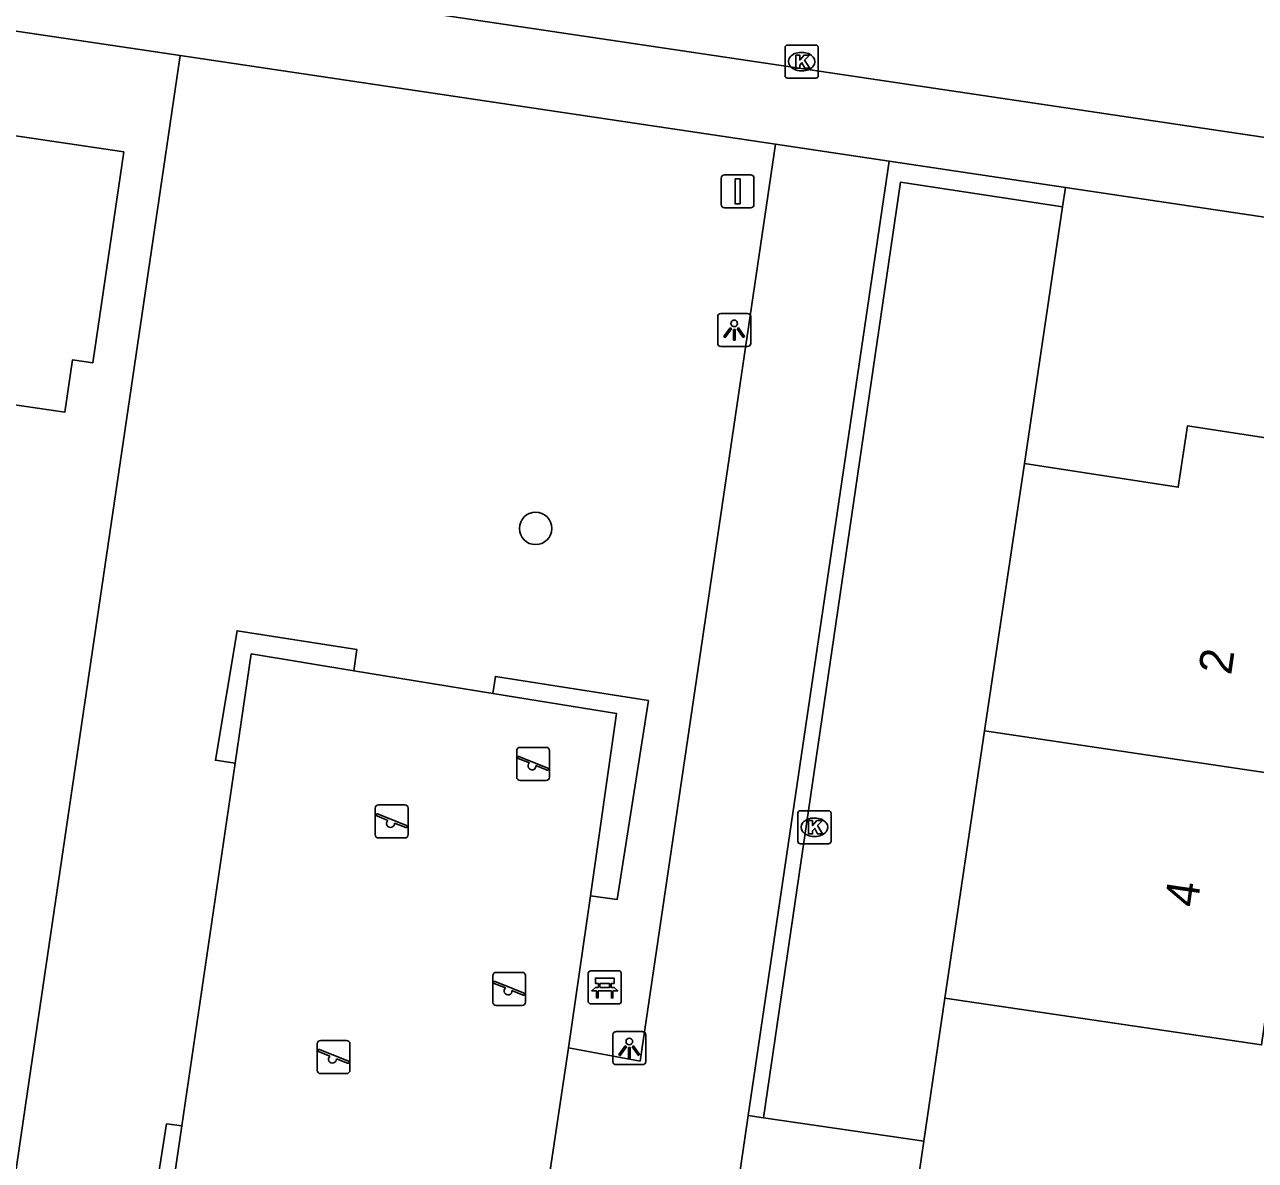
# Model space of a CAD drawing. Extents: x 164150 to 165261, y 382513 to 383432.
# Drawn here: x 164487.69 to 164524.87, y 383153.66 to 383187.97 of the extents above; entities that cross this region are included whole.
import ezdxf

# ---------------------------------------------------------------- set-up
doc = ezdxf.new("R2010")
doc.units = 0
for name, color, linetype in [('IMGEO_Bank', 7, 'Continuous'), ('IMGEO_Boom', 7, 'Continuous'), ('IMGEO_Groenvoorziening', 7, 'Continuous'), ('IMGEO_Haag', 7, 'Continuous'), ('IMGEO_Hek', 7, 'Continuous'), ('IMGEO_Kolk', 7, 'Continuous'), ('IMGEO_Lichtpunt', 7, 'Continuous'), ('IMGEO_Muur', 7, 'Continuous'), ('IMGEO_Pand', 7, 'Continuous'), ('IMGEO_Pand_nummerreeks', 7, 'Continuous'), ('IMGEO_Rijbaan_lokaal_open', 7, 'Continuous'), ('IMGEO_Speelvoorziening', 7, 'Continuous'), ('IMGEO_Verkeersbordpaal', 7, 'Continuous'), ('IMGEO_Voetpad_gesloten', 7, 'Continuous'), ('IMGEO_Voetpad_halfverhard', 7, 'Continuous'), ('IMGEO_Voetpad_open', 7, 'Continuous')]:
    doc.layers.add(name, color=color, linetype=linetype)

msp = doc.modelspace()

# ---------------------------------------------------------------- linework, layer by layer
at = {"layer": 'IMGEO_Bank'}
for p, q in [((164504.719, 383158.457), (164504.719, 383159.298)), ((164504.719, 383159.298), (164504.719, 383158.457)), ((164504.794, 383159.382), (164505.635, 383159.382)), ((164505.635, 383159.382), (164504.794, 383159.382)), ((164505.719, 383159.307), (164505.719, 383158.466)), ((164505.719, 383158.466), (164505.719, 383159.307)), ((164505.028, 383158.888), (164505.028, 383158.994)), ((164505.072, 383158.994), (164505.072, 383158.888)), ((164505.36, 383159), (164505.078, 383159)), ((164505.366, 383158.888), (164505.366, 383158.994)), ((164505.41, 383158.994), (164505.41, 383158.888)), ((164505.416, 383158.78), (164505.023, 383158.78)), ((164505.078, 383158.882), (164505.36, 383158.882)), ((164505.644, 383158.382), (164504.803, 383158.382)), ((164504.803, 383158.382), (164505.644, 383158.382))]:
    msp.add_line(p, q, dxfattribs=at)
for points in [[(164505.022, 383159), (164504.936, 383159), (164504.936, 383159.161), (164505.499, 383159.161), (164505.499, 383159), (164505.416, 383159)], [(164504.966, 383158.78), (164504.824, 383158.78), (164504.936, 383158.882), (164505.022, 383158.882)], [(164505.016, 383158.773), (164505.016, 383158.566), (164504.973, 383158.566), (164504.973, 383158.773)], [(164505.416, 383158.882), (164505.499, 383158.882), (164505.611, 383158.78), (164505.472, 383158.78)], [(164505.466, 383158.773), (164505.466, 383158.566), (164505.422, 383158.566), (164505.422, 383158.773)]]:
    msp.add_lwpolyline(points, dxfattribs=at)
for centre, radius, start, end in [((164504.797, 383159.304), 0.0779, 92.4484, 184.2845), ((164504.797, 383159.304), 0.0779, 92.4484, 184.2845), ((164505.641, 383159.304), 0.0779, 2.4484, 94.2845), ((164505.641, 383159.304), 0.0779, 2.4484, 94.2845), ((164505.021, 383158.993), 0.00671, 2.8957, 87.1043), ((164505.078, 383158.993), 0.00671, 92.8957, 177.1043), ((164505.36, 383158.993), 0.00671, 2.8957, 87.1043), ((164505.417, 383158.993), 0.00671, 92.8957, 177.1043), ((164504.966, 383158.773), 0.00671, 2.8957, 87.1043), ((164505.023, 383158.773), 0.00671, 92.8957, 177.1043), ((164505.021, 383158.889), 0.00671, 272.8957, 357.1043), ((164505.078, 383158.889), 0.00671, 182.8957, 267.1043), ((164505.36, 383158.889), 0.00671, 272.8957, 357.1043), ((164505.417, 383158.889), 0.00671, 182.8957, 267.1043), ((164505.415, 383158.773), 0.00671, 2.8957, 87.1043), ((164505.472, 383158.773), 0.00671, 92.8957, 177.1043), ((164504.797, 383158.46), 0.0779, 182.4484, 274.2845), ((164504.797, 383158.46), 0.0779, 182.4484, 274.2845), ((164505.641, 383158.46), 0.0779, 272.4484, 4.2845), ((164505.641, 383158.46), 0.0779, 272.4484, 4.2845)]:
    msp.add_arc(centre, radius, start, end, dxfattribs=at)
at = {"layer": 'IMGEO_Boom'}
msp.add_circle((164503.13, 383172.747), 0.489, dxfattribs=at)
at = {"layer": 'IMGEO_Groenvoorziening'}
for points in [[(164471.706, 383047.448), (164472.669, 383053.926), (164475.824, 383075.164), (164477.779, 383088.109), (164480.994, 383109.14), (164482.781, 383122.124), (164485.913, 383143.071), (164487.83, 383156.078), (164491.989, 383184.295), (164492.391, 383187.03)], [(164519.048, 383182.465), (164517.895, 383174.707)], [(164497.639, 383168.449), (164501.839, 383167.764)], [(164492.441, 383154.698), (164494.054, 383165.655)], [(164504.784, 383161.653), (164504.121, 383157.056)], [(164515.497, 383158.557), (164514.861, 383154.235)]]:
    msp.add_lwpolyline(points, dxfattribs=at)
at = {"layer": 'IMGEO_Haag'}
for points in [[(164510.019, 383154.941), (164514.153, 383183.206), (164519.048, 383182.465)], [(164519.135, 383183.048), (164519.048, 383182.465)], [(164494.054, 383165.655), (164493.459, 383165.742), (164494.111, 383169.655), (164497.732, 383169.088), (164497.639, 383168.449)], [(164497.639, 383168.449), (164494.539, 383168.955), (164494.054, 383165.655)], [(164501.839, 383167.764), (164501.914, 383168.278), (164506.54, 383167.546), (164505.591, 383161.535), (164504.784, 383161.653)], [(164504.784, 383161.653), (164505.577, 383167.155), (164501.839, 383167.764)], [(164492.441, 383154.698), (164491.984, 383154.765), (164490.143, 383143.122), (164490.734, 383143.036), (164491.735, 383149.899)], [(164491.735, 383149.899), (164492.441, 383154.698)]]:
    msp.add_lwpolyline(points, dxfattribs=at)
at = {"layer": 'IMGEO_Hek'}
msp.add_lwpolyline([(164491.989, 383184.295), (164487.83, 383156.078)], dxfattribs=at)
at = {"layer": 'IMGEO_Kolk'}
for p, q in [((164510.666, 383186.422), (164510.666, 383187.274)), ((164510.741, 383187.348), (164511.593, 383187.348)), ((164511.667, 383187.274), (164511.667, 383186.422)), ((164511.154, 383187.128), (164511.179, 383187.128)), ((164511.177, 383186.568), (164511.152, 383186.568)), ((164511.593, 383186.348), (164510.741, 383186.348)), ((164511.054, 383163.293), (164511.054, 383164.145)), ((164511.129, 383164.219), (164511.981, 383164.219)), ((164512.055, 383164.145), (164512.055, 383163.293)), ((164511.542, 383163.999), (164511.567, 383163.999)), ((164511.565, 383163.439), (164511.54, 383163.439)), ((164511.981, 383163.219), (164511.129, 383163.219))]:
    msp.add_line(p, q, dxfattribs=at)
for points in [[(164510.666, 383186.422), (164510.666, 383187.274)], [(164510.741, 383187.348), (164511.593, 383187.348)], [(164511.667, 383187.274), (164511.667, 383186.422)], [(164510.987, 383187.048), (164511.11, 383187.048), (164511.11, 383186.897), (164511.24, 383187.048), (164511.404, 383187.048), (164511.258, 383186.897), (164511.411, 383186.648), (164511.259, 383186.648), (164511.174, 383186.812), (164511.11, 383186.745), (164511.11, 383186.648), (164510.987, 383186.648), (164510.987, 383187.048)], [(164511.593, 383186.348), (164510.741, 383186.348)], [(164511.054, 383163.293), (164511.054, 383164.145)], [(164511.129, 383164.219), (164511.981, 383164.219)], [(164512.055, 383164.145), (164512.055, 383163.293)], [(164511.375, 383163.919), (164511.498, 383163.919), (164511.498, 383163.768), (164511.628, 383163.919), (164511.792, 383163.919), (164511.646, 383163.768), (164511.799, 383163.519), (164511.647, 383163.519), (164511.562, 383163.683), (164511.498, 383163.616), (164511.498, 383163.519), (164511.375, 383163.519), (164511.375, 383163.919)], [(164511.981, 383163.219), (164511.129, 383163.219)]]:
    msp.add_lwpolyline(points, dxfattribs=at)
for centre, start, end in [((164510.743, 383187.272), 91.552, 178.448), ((164510.743, 383187.272), 91.552, 178.448), ((164511.591, 383187.272), 1.552, 88.448), ((164511.591, 383187.272), 1.552, 88.448), ((164510.743, 383186.424), 181.552, 268.448), ((164510.743, 383186.424), 181.552, 268.448), ((164511.591, 383186.424), 271.552, 358.448), ((164511.591, 383186.424), 271.552, 358.448), ((164511.131, 383164.143), 91.552, 178.448), ((164511.131, 383164.143), 91.552, 178.448), ((164511.979, 383164.143), 1.552, 88.448), ((164511.979, 383164.143), 1.552, 88.448), ((164511.131, 383163.295), 181.552, 268.448), ((164511.131, 383163.295), 181.552, 268.448), ((164511.979, 383163.295), 271.552, 358.448), ((164511.979, 383163.295), 271.552, 358.448)]:
    msp.add_arc(centre, 0.0765, start, end, dxfattribs=at)
for centre, major_axis, ratio, start_param, end_param in [((164511.153, 383186.848), (-0.387, 0.002), 0.722429, 4.712389, 7.853982), ((164511.178, 383186.848), (-0.39, 0.002), 0.717154, 1.570796, 4.712389), ((164511.541, 383163.719), (-0.387, 0.002), 0.722429, 4.712389, 7.853982), ((164511.566, 383163.719), (-0.39, 0.002), 0.717154, 1.570796, 4.712389)]:
    msp.add_ellipse(centre, major_axis=major_axis, ratio=ratio, start_param=start_param, end_param=end_param, dxfattribs=at)
at = {"layer": 'IMGEO_Lichtpunt'}
for p, q in [((164508.633, 383179.144), (164508.633, 383178.337)), ((164508.633, 383179.144), (164508.633, 383178.337)), ((164509.535, 383179.239), (164508.727, 383179.239)), ((164509.535, 383179.239), (164508.727, 383179.239)), ((164509.629, 383178.337), (164509.629, 383179.144)), ((164509.629, 383178.337), (164509.629, 383179.144)), ((164508.727, 383178.243), (164509.535, 383178.243)), ((164508.727, 383178.243), (164509.535, 383178.243)), ((164505.462, 383157.45), (164505.462, 383156.643)), ((164505.462, 383157.45), (164505.462, 383156.643)), ((164506.364, 383157.545), (164505.556, 383157.545)), ((164506.364, 383157.545), (164505.556, 383157.545)), ((164506.458, 383156.643), (164506.458, 383157.45)), ((164506.458, 383156.643), (164506.458, 383157.45)), ((164505.556, 383156.549), (164506.364, 383156.549)), ((164505.556, 383156.549), (164506.364, 383156.549))]:
    msp.add_line(p, q, dxfattribs=at)
for points in [[(164509.007, 383178.808), (164509.046, 383178.78), (164508.858, 383178.518), (164508.82, 383178.545), (164509.007, 383178.808)], [(164509.109, 383178.76), (164509.156, 383178.76), (164509.156, 383178.438), (164509.109, 383178.438), (164509.109, 383178.76)], [(164509.219, 383178.78), (164509.257, 383178.807), (164509.444, 383178.545), (164509.405, 383178.517), (164509.219, 383178.78)], [(164505.836, 383157.114), (164505.875, 383157.086), (164505.687, 383156.824), (164505.649, 383156.851), (164505.836, 383157.114)], [(164505.938, 383157.066), (164505.985, 383157.066), (164505.985, 383156.744), (164505.938, 383156.744), (164505.938, 383157.066)], [(164506.048, 383157.086), (164506.086, 383157.113), (164506.273, 383156.851), (164506.234, 383156.823), (164506.048, 383157.086)]]:
    msp.add_lwpolyline(points, dxfattribs=at)
for centre in [(164509.132, 383178.942), (164505.961, 383157.248)]:
    msp.add_circle(centre, 0.0994, dxfattribs=at)
for centre, start, end in [((164508.727, 383179.144), 90, 180), ((164508.727, 383179.144), 90, 180), ((164509.535, 383179.144), 0, 90), ((164509.535, 383179.144), 0, 90), ((164508.727, 383178.337), 180, 270), ((164508.727, 383178.337), 180, 270), ((164509.535, 383178.337), 270, 0), ((164509.535, 383178.337), 270, 360), ((164505.556, 383157.45), 90, 180), ((164505.556, 383157.45), 90, 180), ((164506.364, 383157.45), 0, 90), ((164506.364, 383157.45), 0, 90), ((164505.556, 383156.643), 180, 270), ((164505.556, 383156.643), 180, 270), ((164506.364, 383156.643), 270, 0), ((164506.364, 383156.643), 270, 360)]:
    msp.add_arc(centre, 0.0946, start, end, dxfattribs=at)
at = {"layer": 'IMGEO_Muur'}
for points in [[(164519.048, 383182.465), (164519.135, 383183.048)], [(164517.895, 383174.707), (164519.048, 383182.465)], [(164514.861, 383154.235), (164515.497, 383158.557)], [(164514.577, 383152.304), (164514.861, 383154.235)]]:
    msp.add_lwpolyline(points, dxfattribs=at)
at = {"layer": 'IMGEO_Pand'}
for points in [[(164480.232, 383177.526), (164480.455, 383179.112), (164479.851, 383179.203), (164480.809, 383185.584), (164490.686, 383184.123), (164489.751, 383177.748), (164489.137, 383177.838), (164488.905, 383176.255), (164480.232, 383177.526)], [(164517.895, 383174.707), (164522.543, 383173.993), (164522.828, 383175.849), (164527.622, 383175.113), (164527.023, 383171.211), (164527.109, 383171.198), (164526.238, 383165.217)], [(164516.695, 383166.636), (164517.895, 383174.707)], [(164516.695, 383166.636), (164515.497, 383158.557)], [(164526.238, 383165.217), (164516.695, 383166.636)], [(164526.238, 383165.217), (164525.062, 383157.145), (164515.497, 383158.557)]]:
    msp.add_lwpolyline(points, dxfattribs=at)
at = {"layer": 'IMGEO_Rijbaan_lokaal_open'}
msp.add_lwpolyline([(164551.499, 383180.681), (164539.055, 383182.494), (164484.669, 383190.59)], dxfattribs=at)
at = {"layer": 'IMGEO_Speelvoorziening'}
for p, q in [((164502.559, 383165.234), (164502.559, 383166.034)), ((164502.559, 383166.034), (164502.559, 383165.234)), ((164502.659, 383166.134), (164503.449, 383166.134)), ((164503.449, 383166.134), (164502.659, 383166.134)), ((164503.549, 383166.034), (164503.549, 383165.234)), ((164503.549, 383165.234), (164503.549, 383166.034)), ((164502.942, 383165.662), (164502.603, 383165.799)), ((164502.628, 383165.859), (164503.504, 383165.506)), ((164503.48, 383165.446), (164503.14, 383165.583)), ((164503.449, 383165.134), (164502.659, 383165.134)), ((164502.659, 383165.134), (164503.449, 383165.134)), ((164498.286, 383163.496), (164498.286, 383164.296)), ((164498.286, 383164.296), (164498.286, 383163.496)), ((164498.355, 383164.121), (164499.231, 383163.768)), ((164498.386, 383164.396), (164499.176, 383164.396)), ((164499.176, 383164.396), (164498.386, 383164.396)), ((164499.276, 383164.296), (164499.276, 383163.496)), ((164499.276, 383163.496), (164499.276, 383164.296)), ((164498.669, 383163.924), (164498.33, 383164.061)), ((164499.207, 383163.708), (164498.867, 383163.845)), ((164499.176, 383163.396), (164498.386, 383163.396)), ((164498.386, 383163.396), (164499.176, 383163.396)), ((164501.935, 383159.337), (164502.725, 383159.337)), ((164502.725, 383159.337), (164501.935, 383159.337)), ((164501.835, 383158.437), (164501.835, 383159.237)), ((164501.835, 383159.237), (164501.835, 383158.437)), ((164502.218, 383158.865), (164501.879, 383159.002)), ((164501.904, 383159.062), (164502.78, 383158.709)), ((164502.825, 383159.237), (164502.825, 383158.437)), ((164502.825, 383158.437), (164502.825, 383159.237)), ((164502.756, 383158.649), (164502.416, 383158.786)), ((164502.725, 383158.337), (164501.935, 383158.337)), ((164501.935, 383158.337), (164502.725, 383158.337)), ((164496.531, 383156.377), (164496.531, 383157.177)), ((164496.531, 383157.177), (164496.531, 383156.377)), ((164496.631, 383157.277), (164497.421, 383157.277)), ((164497.421, 383157.277), (164496.631, 383157.277)), ((164497.521, 383157.177), (164497.521, 383156.377)), ((164497.521, 383156.377), (164497.521, 383157.177)), ((164496.914, 383156.805), (164496.575, 383156.942)), ((164496.6, 383157.002), (164497.476, 383156.649)), ((164497.452, 383156.589), (164497.112, 383156.726)), ((164497.421, 383156.277), (164496.631, 383156.277)), ((164496.631, 383156.277), (164497.421, 383156.277))]:
    msp.add_line(p, q, dxfattribs=at)
for centre, radius, start, end in [((164502.659, 383166.034), 0.1, 90, 180), ((164502.659, 383166.034), 0.1, 90, 180), ((164503.449, 383166.034), 0.1, 0, 90), ((164503.449, 383166.034), 0.1, 360, 90), ((164502.616, 383165.829), 0.0327, 68.078, 248.078), ((164503.021, 383165.572), 0.12, 130.9928, 5.1632), ((164502.659, 383165.234), 0.1, 180, 270), ((164502.659, 383165.234), 0.1, 180, 270), ((164503.449, 383165.234), 0.1, 270, 0), ((164503.449, 383165.234), 0.1, 270, 0), ((164503.492, 383165.476), 0.0327, 248.078, 68.078), ((164498.386, 383164.296), 0.1, 90, 180), ((164498.386, 383164.296), 0.1, 90, 180), ((164498.343, 383164.091), 0.0327, 68.078, 248.078), ((164499.176, 383164.296), 0.1, 0, 90), ((164499.176, 383164.296), 0.1, 360, 90), ((164498.748, 383163.834), 0.12, 130.9928, 5.1632), ((164499.219, 383163.738), 0.0327, 248.078, 68.078), ((164498.386, 383163.496), 0.1, 180, 270), ((164498.386, 383163.496), 0.1, 180, 270), ((164499.176, 383163.496), 0.1, 270, 0), ((164499.176, 383163.496), 0.1, 270, 0), ((164501.935, 383159.237), 0.1, 90, 180), ((164501.935, 383159.237), 0.1, 90, 180), ((164502.725, 383159.237), 0.1, 0, 90), ((164502.725, 383159.237), 0.1, 360, 90), ((164501.892, 383159.032), 0.0327, 68.078, 248.078), ((164502.297, 383158.775), 0.12, 130.9928, 5.1632), ((164502.768, 383158.679), 0.0327, 248.078, 68.078), ((164501.935, 383158.437), 0.1, 180, 270), ((164501.935, 383158.437), 0.1, 180, 270), ((164502.725, 383158.437), 0.1, 270, 0), ((164502.725, 383158.437), 0.1, 270, 0), ((164496.631, 383157.177), 0.1, 90, 180), ((164496.631, 383157.177), 0.1, 90, 180), ((164497.421, 383157.177), 0.1, 0, 90), ((164497.421, 383157.177), 0.1, 360, 90), ((164496.588, 383156.972), 0.0327, 68.078, 248.078), ((164496.993, 383156.715), 0.12, 130.9928, 5.1632), ((164496.631, 383156.377), 0.1, 180, 270), ((164496.631, 383156.377), 0.1, 180, 270), ((164497.421, 383156.377), 0.1, 270, 0), ((164497.421, 383156.377), 0.1, 270, 0), ((164497.464, 383156.619), 0.0327, 248.078, 68.078)]:
    msp.add_arc(centre, radius, start, end, dxfattribs=at)
at = {"layer": 'IMGEO_Verkeersbordpaal'}
for p, q in [((164508.737, 383182.531), (164508.737, 383183.331)), ((164508.737, 383183.331), (164508.737, 383182.531)), ((164508.837, 383183.431), (164509.627, 383183.431)), ((164509.627, 383183.431), (164508.837, 383183.431)), ((164509.727, 383183.331), (164509.727, 383182.531)), ((164509.727, 383182.531), (164509.727, 383183.331)), ((164509.627, 383182.431), (164508.837, 383182.431)), ((164508.837, 383182.431), (164509.627, 383182.431))]:
    msp.add_line(p, q, dxfattribs=at)
msp.add_lwpolyline([(164509.157, 383183.306), (164509.307, 383183.306), (164509.307, 383182.556), (164509.157, 383182.556), (164509.157, 383183.306)], dxfattribs=at)
for centre, start, end in [((164508.837, 383183.331), 90, 180), ((164508.837, 383183.331), 90, 180), ((164509.627, 383183.331), 0, 90), ((164509.627, 383183.331), 360, 90), ((164508.837, 383182.531), 180, 270), ((164508.837, 383182.531), 180, 270), ((164509.627, 383182.531), 270, 0), ((164509.627, 383182.531), 270, 0)]:
    msp.add_arc(centre, 0.1, start, end, dxfattribs=at)
at = {"layer": 'IMGEO_Voetpad_gesloten'}
for points in [[(164510.374, 383184.352), (164506.288, 383156.657), (164504.121, 383157.056)], [(164510.374, 383184.352), (164513.815, 383183.84)], [(164509.556, 383155.009), (164513.815, 383183.84)], [(164504.121, 383157.056), (164503.159, 383150.601)], [(164509.556, 383155.009), (164509.271, 383153.078)]]:
    msp.add_lwpolyline(points, dxfattribs=at)
at = {"layer": 'IMGEO_Voetpad_halfverhard'}
for points in [[(164510.019, 383154.941), (164509.556, 383155.009)], [(164514.861, 383154.235), (164510.019, 383154.941)], [(164514.577, 383152.304), (164514.861, 383154.235)]]:
    msp.add_lwpolyline(points, dxfattribs=at)
at = {"layer": 'IMGEO_Voetpad_open'}
for points in [[(164482.417, 383188.515), (164492.391, 383187.03)], [(164492.391, 383187.03), (164510.374, 383184.352)], [(164513.815, 383183.84), (164519.135, 383183.048)], [(164519.135, 383183.048), (164540.017, 383179.939), (164553.746, 383177.932)]]:
    msp.add_lwpolyline(points, dxfattribs=at)

# ---------------------------------------------------------------- texts
at = {"layer": 'IMGEO_Pand_nummerreeks'}
for s, rotation, p in [('2', 81.7152, (164524.14, 383168.296)), ('4', 81.7135, (164523.117, 383161.275))]:
    msp.add_text(s, height=1, rotation=rotation, dxfattribs=at).set_placement(p)

doc.saveas('drawing.dxf')
